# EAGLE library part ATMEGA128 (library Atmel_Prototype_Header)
MICROCONTROLLER 128 Kbytes FLASH 4 Kbytes SRAM 4 Kbytes EEPROM DUAL USART 8-channel 10 bit ADC
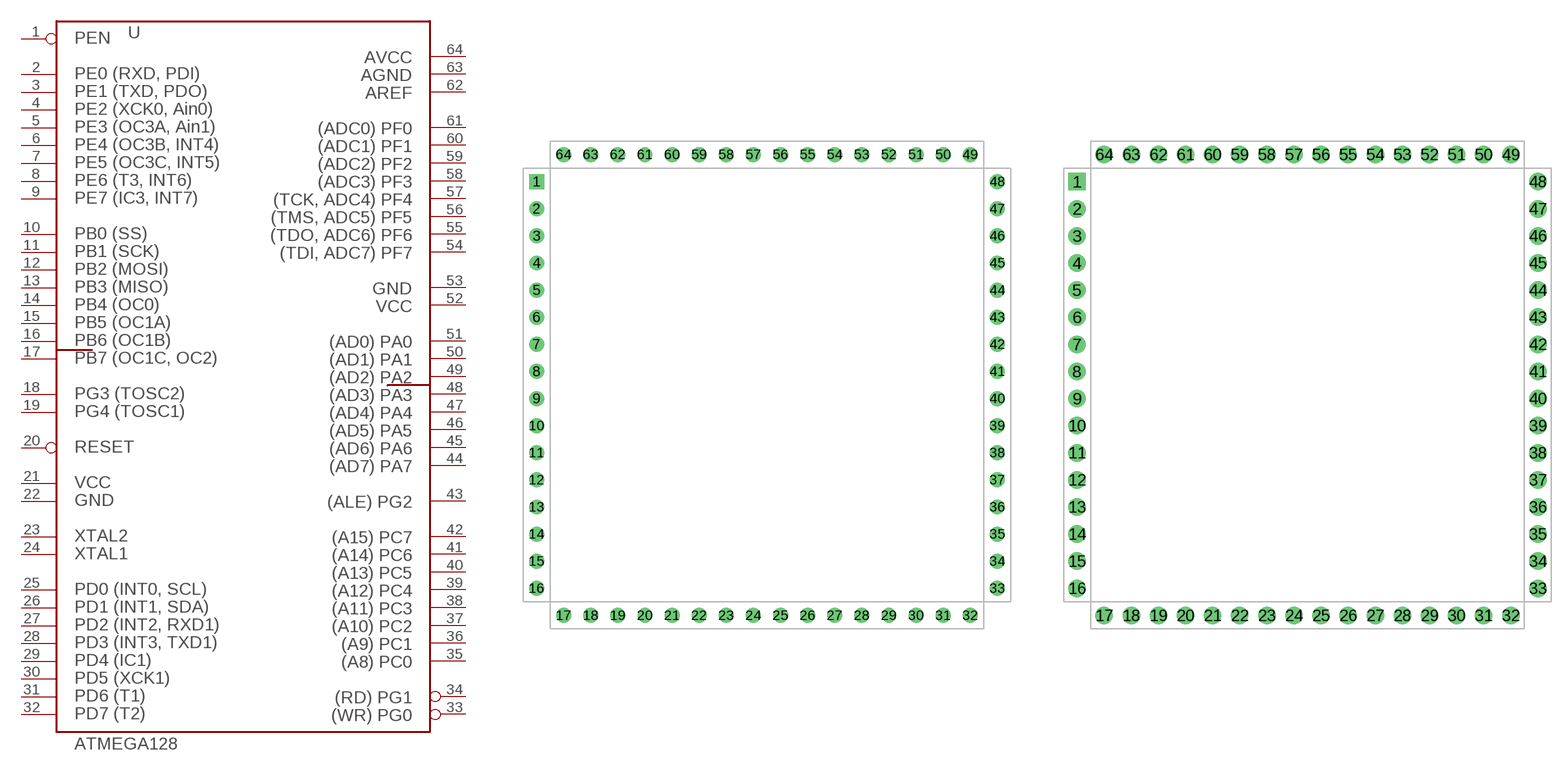
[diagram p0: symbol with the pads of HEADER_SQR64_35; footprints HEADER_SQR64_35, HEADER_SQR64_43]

Designator prefix U

## ATMEGA128_SINGLE64_35  [HEADER_SQR64_35]
1  1  in
2  2
3  3
4  4
5  5
6  6
7  7
8  8
9  9
10  10
11  11
12  12
13  13
14  14
15  15
16  16
17  17
18  18
19  19
20  20  in
21  21  pwr
22  22  pwr
23  23
24  24
25  25
26  26
27  27
28  28
29  29
30  30
31  31
32  32
33  33
34  34
35  35  out
36  36  out
37  37  out
38  38  out
39  39  out
40  40  out
41  41  out
42  42  out
43  43
44  44
45  45
46  46
47  47
48  48
49  49
50  50
51  51
52  52  pwr
53  53  pwr
54  54  in
55  55  in
56  56  in
57  57  in
58  58  in
59  59  in
60  60  in
61  61  in
62  62
63  63
64  64

## ATMEGA128_SINGLE64_43  [HEADER_SQR64_43]
Pads as for HEADER_SQR64_35

## ATMEGA128_TQPF  [TQFP64]
Pads as for HEADER_SQR64_35

## ATMEGA128_DUAL64_43  [HEADER_DUALSQR64_43]
Pads as for HEADER_SQR64_35

## ATMEGA128_DUAL64_35  [HEADER_DUALSQR64_35]
Pads as for HEADER_SQR64_35

## Footprint HEADER_SQR64_35 (pad centres in mm)
drill 0.889 square: 1 -10.16,11.43
drill 0.889 round: 2 -10.16,8.89; 3 -10.16,6.35; 4 -10.16,3.81; 5 -10.16,1.27; 6 -10.16,-1.27; 7 -10.16,-3.81; 8 -10.16,-6.35; 9 -10.16,-8.89; 10 -10.16,-11.43; 11 -10.16,-13.97; 12 -10.16,-16.51; 13 -10.16,-19.05; 14 -10.16,-21.59; 15 -10.16,-24.13; 16 -10.16,-26.67; 17 -7.62,-29.21; 18 -5.08,-29.21; 19 -2.54,-29.21; 20 0,-29.21; 21 2.54,-29.21; 22 5.08,-29.21; 23 7.62,-29.21; 24 10.16,-29.21; 25 12.7,-29.21; 26 15.24,-29.21; 27 17.78,-29.21; 28 20.32,-29.21; 29 22.86,-29.21; 30 25.4,-29.21; 31 27.94,-29.21; 32 30.48,-29.21; 33 33.02,-26.67; 34 33.02,-24.13; 35 33.02,-21.59; 36 33.02,-19.05; 37 33.02,-16.51; 38 33.02,-13.97; 39 33.02,-11.43; 40 33.02,-8.89; 41 33.02,-6.35; 42 33.02,-3.81; 43 33.02,-1.27; 44 33.02,1.27; 45 33.02,3.81; 46 33.02,6.35; 47 33.02,8.89; 48 33.02,11.43; 49 30.48,13.97; 50 27.94,13.97; 51 25.4,13.97; 52 22.86,13.97; 53 20.32,13.97; 54 17.78,13.97; 55 15.24,13.97; 56 12.7,13.97; 57 10.16,13.97; 58 7.62,13.97; 59 5.08,13.97; 60 2.54,13.97; 61 0,13.97; 62 -2.54,13.97; 63 -5.08,13.97; 64 -7.62,13.97

## Footprint HEADER_SQR64_43 (pad centres in mm)
drill 1.092 square: 1 -21.59,19.05
drill 1.092 round: 2 -21.59,16.51; 3 -21.59,13.97; 4 -21.59,11.43; 5 -21.59,8.89; 6 -21.59,6.35; 7 -21.59,3.81; 8 -21.59,1.27; 9 -21.59,-1.27; 10 -21.59,-3.81; 11 -21.59,-6.35; 12 -21.59,-8.89; 13 -21.59,-11.43; 14 -21.59,-13.97; 15 -21.59,-16.51; 16 -21.59,-19.05; 17 -19.05,-21.59; 18 -16.51,-21.59; 19 -13.97,-21.59; 20 -11.43,-21.59; 21 -8.89,-21.59; 22 -6.35,-21.59; 23 -3.81,-21.59; 24 -1.27,-21.59; 25 1.27,-21.59; 26 3.81,-21.59; 27 6.35,-21.59; 28 8.89,-21.59; 29 11.43,-21.59; 30 13.97,-21.59; 31 16.51,-21.59; 32 19.05,-21.59; 33 21.59,-19.05; 34 21.59,-16.51; 35 21.59,-13.97; 36 21.59,-11.43; 37 21.59,-8.89; 38 21.59,-6.35; 39 21.59,-3.81; 40 21.59,-1.27; 41 21.59,1.27; 42 21.59,3.81; 43 21.59,6.35; 44 21.59,8.89; 45 21.59,11.43; 46 21.59,13.97; 47 21.59,16.51; 48 21.59,19.05; 49 19.05,21.59; 50 16.51,21.59; 51 13.97,21.59; 52 11.43,21.59; 53 8.89,21.59; 54 6.35,21.59; 55 3.81,21.59; 56 1.27,21.59; 57 -1.27,21.59; 58 -3.81,21.59; 59 -6.35,21.59; 60 -8.89,21.59; 61 -11.43,21.59; 62 -13.97,21.59; 63 -16.51,21.59; 64 -19.05,21.59

## Footprint TQFP64 (pad centres in mm)
Thin Plasic Quad Flat Package
smd 1.194 x 0.559: 1 -7.76,5.905; 2 -7.76,5.118; 3 -7.76,4.331; 4 -7.76,3.543; 5 -7.76,2.756; 6 -7.76,1.968; 7 -7.76,1.181; 8 -7.76,0.394; 9 -7.76,-0.394; 10 -7.76,-1.181; 11 -7.76,-1.968; 12 -7.76,-2.756; 13 -7.76,-3.543; 14 -7.76,-4.331; 15 -7.76,-5.118; 16 -7.76,-5.905; 33 7.76,-5.905; 34 7.76,-5.118; 35 7.76,-4.331; 36 7.76,-3.543; 37 7.76,-2.756; 38 7.76,-1.968; 39 7.76,-1.181; 40 7.76,-0.394; 41 7.76,0.394; 42 7.76,1.181; 43 7.76,1.968; 44 7.76,2.756; 45 7.76,3.543; 46 7.76,4.331; 47 7.76,5.118; 48 7.76,5.905
smd 0.559 x 1.194: 17 -5.905,-7.76; 18 -5.118,-7.76; 19 -4.331,-7.76; 20 -3.543,-7.76; 21 -2.756,-7.76; 22 -1.968,-7.76; 23 -1.181,-7.76; 24 -0.394,-7.76; 25 0.394,-7.76; 26 1.181,-7.76; 27 1.968,-7.76; 28 2.756,-7.76; 29 3.543,-7.76; 30 4.331,-7.76; 31 5.118,-7.76; 32 5.905,-7.76; 49 5.905,7.76; 50 5.118,7.76; 51 4.331,7.76; 52 3.543,7.76; 53 2.756,7.76; 54 1.968,7.76; 55 1.181,7.76; 56 0.394,7.76; 57 -0.394,7.76; 58 -1.181,7.76; 59 -1.968,7.76; 60 -2.756,7.76; 61 -3.543,7.76; 62 -4.331,7.76; 63 -5.118,7.76; 64 -5.905,7.76

## Footprint HEADER_DUALSQR64_43 (pad centres in mm)
drill 1.1 square: 1 -13.97,8.89
drill 1.1 round: 2 -11.43,8.89; 3 -13.97,6.35; 4 -11.43,6.35; 5 -13.97,3.81; 6 -11.43,3.81; 7 -13.97,1.27; 8 -11.43,1.27; 9 -13.97,-1.27; 10 -11.43,-1.27; 11 -13.97,-3.81; 12 -11.43,-3.81; 13 -13.97,-6.35; 14 -11.43,-6.35; 15 -13.97,-8.89; 16 -11.43,-8.89; 17 -8.89,-13.97; 18 -8.89,-11.43; 19 -6.35,-13.97; 20 -6.35,-11.43; 21 -3.81,-13.97; 22 -3.81,-11.43; 23 -1.27,-13.97; 24 -1.27,-11.43; 25 1.27,-13.97; 26 1.27,-11.43; 27 3.81,-13.97; 28 3.81,-11.43; 29 6.35,-13.97; 30 6.35,-11.43; 31 8.89,-13.97; 32 8.89,-11.43; 33 13.97,-8.89; 34 11.43,-8.89; 35 13.97,-6.35; 36 11.43,-6.35; 37 13.97,-3.81; 38 11.43,-3.81; 39 13.97,-1.27; 40 11.43,-1.27; 41 13.97,1.27; 42 11.43,1.27; 43 13.97,3.81; 44 11.43,3.81; 45 13.97,6.35; 46 11.43,6.35; 47 13.97,8.89; 48 11.43,8.89; 49 8.89,13.97; 50 8.89,11.43; 51 6.35,13.97; 52 6.35,11.43; 53 3.81,13.97; 54 3.81,11.43; 55 1.27,13.97; 56 1.27,11.43; 57 -1.27,13.97; 58 -1.27,11.43; 59 -3.81,13.97; 60 -3.81,11.43; 61 -6.35,13.97; 62 -6.35,11.43; 63 -8.89,13.97; 64 -8.89,11.43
